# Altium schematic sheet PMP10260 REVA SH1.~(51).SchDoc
size 431 x 279 mm; Date: Not shown in title block; ApprovedBy: Not shown in title block; CheckedBy: Not shown in title block; Author: Not shown in title block; CompanyName: Not shown in title block; Engineer: Not shown in title block; Organization: Not shown in title block; Address1: Not shown in title block; Address2: Not shown in title block; Address3: Not shown in title block; Address4: Not shown in title block; DocumentNumber: 1; Revision: Use project parameter SCH_Rev; SheetNumber: 1; SheetTotal: 3; PageSetup: Record=PageOptions|CenterHorizontal=True|CenterVertical=True|PrintScale=1.00|XCorrection=1.00|YCorrection=1.00|PrintKind=0|BorderSize=5000000|LeftOffset=0|BottomOffset=0|Orientation=2|PaperLength=1000|PaperWidth=1000|Scale=100|PaperSource=15|PrintQuality=600|MediaType=1|DitherType=10|PaperKind=Letter|PrintScaleMode=1
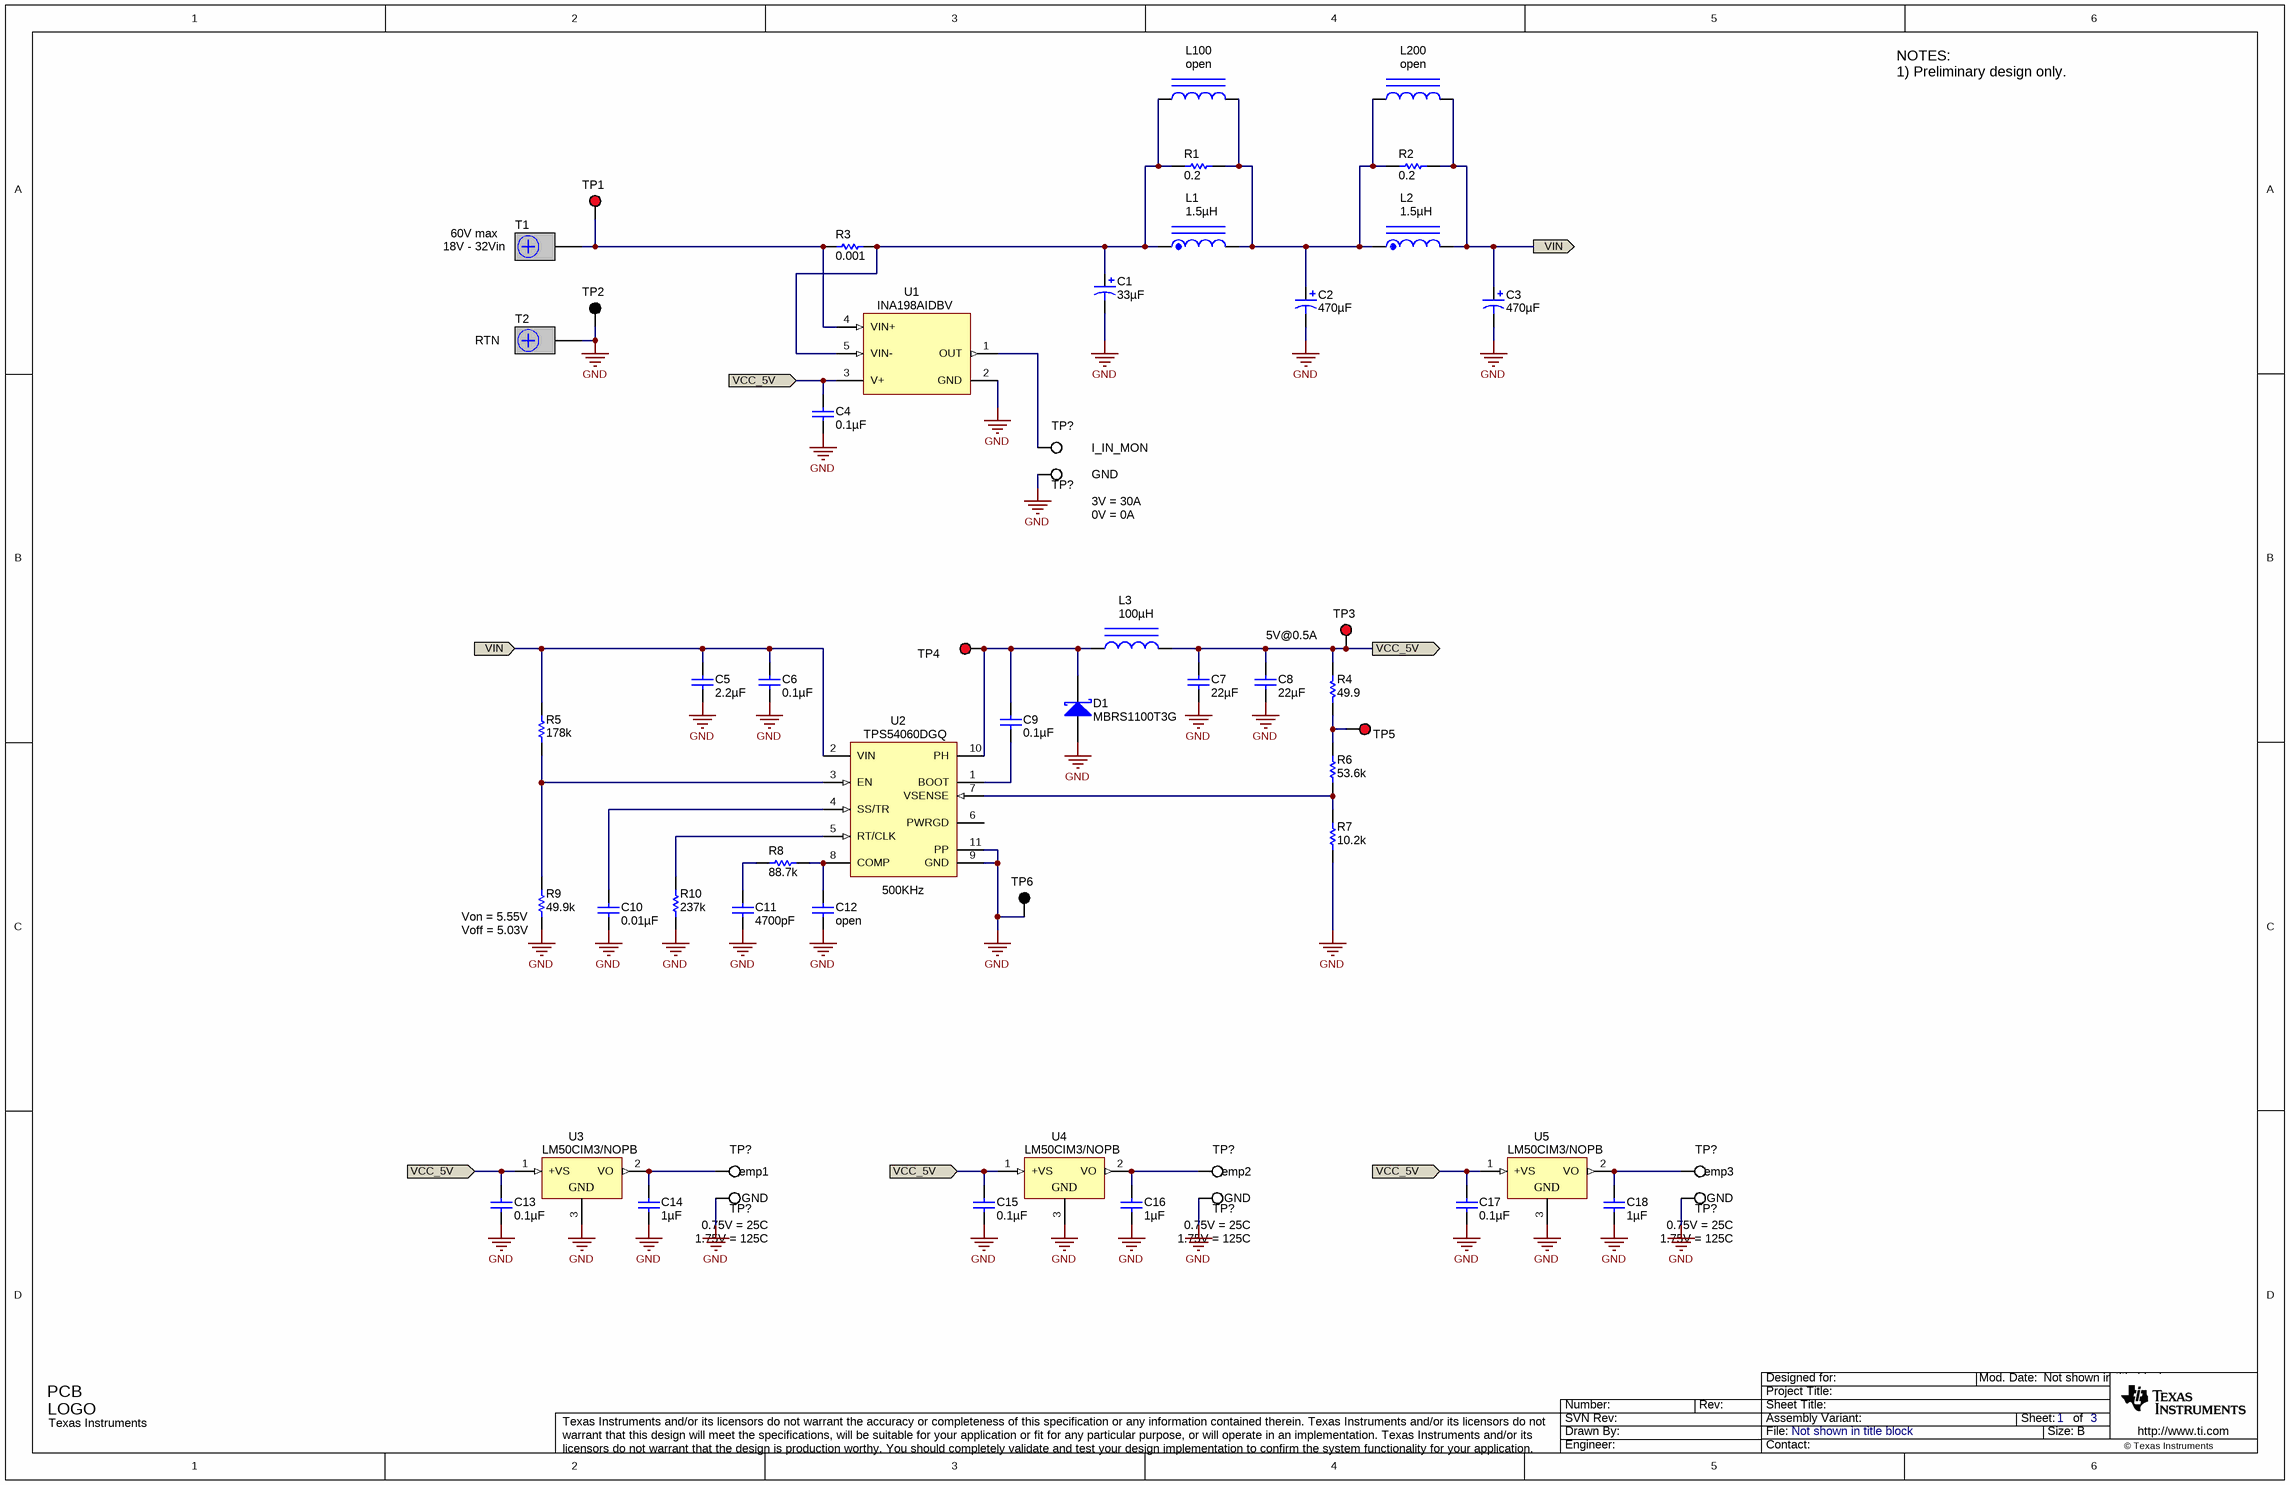
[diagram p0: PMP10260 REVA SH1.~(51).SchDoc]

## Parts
(Parts that share a designator on the sheet are numbered #1, #2 ... from top to bottom, then left to right.)
C1  ValueDisplayed: 33µF  [SXV_E12]  (hidden comment: 63SXV33M)
C2  ValueDisplayed: 470µF  [ZLH_1250x2500]  (hidden comment: 63ZLH470M12.5X25)
C3  ValueDisplayed: 470µF  [ZLH_1250x2500]  (hidden comment: 63ZLH470M12.5X25)
C4  ValueDisplayed: 0.1µF  [0603L]  (hidden comment: C1608X7R1H104K)
C5  ValueDisplayed: 2.2µF  [1210]  (hidden comment: GRM32ER72A225KA35L)
C6  ValueDisplayed: 0.1µF  [0603]  (hidden comment: GRM188R72A104KA35D)
C7  ValueDisplayed: 22µF  [1210]  (hidden comment: C3225X7R1C226M)
C8  ValueDisplayed: 22µF  [1210]  (hidden comment: C3225X7R1C226M)
C9  ValueDisplayed: 0.1µF  [0603]  (hidden comment: C1608X7R1H104K)
C10  ValueDisplayed: 0.01µF  [0603]  (hidden comment: C1608X7R1H103K)
C11  ValueDisplayed: 4700pF  [0603]  (hidden comment: C1608C0G1H472J)
C12  ValueDisplayed: open  [0603]
C13  ValueDisplayed: 0.1µF  [0603]  (hidden comment: C1608X7R1H104K)
C14  ValueDisplayed: 1µF  [0603]  (hidden comment: C1608X7R1E105K080AB)
C15  ValueDisplayed: 0.1µF  [0603]  (hidden comment: C1608X7R1H104K)
C16  ValueDisplayed: 1µF  [0603]  (hidden comment: C1608X7R1E105K080AB)
C17  ValueDisplayed: 0.1µF  [0603]  (hidden comment: C1608X7R1H104K)
C18  ValueDisplayed: 1µF  [0603]  (hidden comment: C1608X7R1E105K080AB)
D1  MBRS1100T3G  [SMB]
L1  ValueDisplayed: 1.5µH  [IND_PG1096]  (hidden comment: PG1096.152NL)
L2  ValueDisplayed: 1.5µH  [IND_PG1096]  (hidden comment: PG1096.152NL)
L3  ValueDisplayed: 100µH  [MSS1048]  (hidden comment: MSS1048-104MLB)
L100  ValueDisplayed: open  [SER2918]
L200  ValueDisplayed: open  [SER2918]
Logo1  Texas Instruments  [TI_Stacked_Overlay_Small]  (no BOM)
R1  value 0.2  [2512]  (hidden comment: CSRN2512FKR200)
R2  value 0.2  [2512]  (hidden comment: CSRN2512FKR200)
R3  value 0.001  [CSS2725_0005]  (hidden comment: CSS2725FT1L00)
R4  value 49.9  [0603]  (hidden comment: CRCW060349R9FKEA)
R5  value 178k  [0603]  (hidden comment: CRCW0603178KFKEA)
R6  value 53.6k  [0603]  (hidden comment: CRCW060353K6FKEA)
R7  value 10.2k  [0603]  (hidden comment: CRCW060310K2FKEA)
R8  value 88.7k  [0603]  (hidden comment: CRCW060388K7FKEA)
R9  value 49.9k  [0603]  (hidden comment: CRCW060349K9FKEA)
R10  value 237k  [0603]  (hidden comment: CRCW0603237KFKEA)
T1  CB35-36-CY  [CB35-36-CY]  (value not drawn)
T2  CB35-36-CY  [CB35-36-CY]  (value not drawn)
TP1  5010  [Keystone5010]  (value not drawn)
TP2  5011  [Keystone5011]  (value not drawn)
TP3  5010  [Keystone5010]  (value not drawn)
TP4  5010  [Keystone5010]  (value not drawn)
TP5  5010  [Keystone5010]  (value not drawn)
TP6  5011  [Keystone5011]  (value not drawn)
TP?#1  5015  [Testpoint_Keystone_Miniature]  (value not drawn)
TP?#2  5015  [Testpoint_Keystone_Miniature]  (value not drawn)
TP?#3  5015  [Testpoint_Keystone_Miniature]  (value not drawn)
TP?#4  5015  [Testpoint_Keystone_Miniature]  (value not drawn)
TP?#5  5015  [Testpoint_Keystone_Miniature]  (value not drawn)
TP?#6  5015  [Testpoint_Keystone_Miniature]  (value not drawn)
TP?#7  5015  [Testpoint_Keystone_Miniature]  (value not drawn)
TP?#8  5015  [Testpoint_Keystone_Miniature]  (value not drawn)
U1  INA198AIDBV  [DBV0005A_N]
U2  TPS54060DGQ  [DGQ0010D_N]
U3  LM50CIM3/NOPB  [MF03A_N]
U4  LM50CIM3/NOPB  [MF03A_N]
U5  LM50CIM3/NOPB  [MF03A_N]

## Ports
VCC_5V, VIN

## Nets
GND: C1.2(-) C2.2(-) C3.2(-) C4.2 C5.2 C6.2 C7.2 C8.2 C10.2 C11.2 C12.2 C13.2 C14.2 C15.2 C16.2 C17.2 C18.2 D1.2(A) R7.1 R9.1 R10.1 T2.1 TP2.1 TP6.1 TP?#2.1 TP?#6.1 TP?#7.1 TP?#8.1 U1.2(GND) U2.9(GND) U2.11(PP) U3.3(GND) U4.3(GND) U5.3(GND)
VCC_5V: C4.1 C7.1 C8.1 C13.1 C15.1 C17.1 L3.2 R4.2 TP3.1 U1.3(V+) U3.1(+VS) U4.1(+VS) U5.1(+VS) ; port VCC_5V
VIN: C3.1(+) C5.1 C6.1 L2.2 L200.2 R2.2 R5.2 U2.2(VIN) ; port VIN
NetC1_1: C1.1(+) L1.1 L100.1 R1.1 R3.2 U1.5(VIN-)
NetC2_1: C2.1(+) L1.2 L2.1 L100.2 L200.1 R1.2 R2.1
NetC9_1: C9.1 D1.1(K) L3.1 TP4.1 U2.10(PH)
NetC9_2: C9.2 U2.1(BOOT)
NetC10_1: C10.1 U2.4(SS/TR)
NetC11_1: C11.1 R8.2
NetC12_1: C12.1 R8.1 U2.8(COMP)
NetC14_1: C14.1 TP?#3.1 U3.2(VO)
NetC16_1: C16.1 TP?#4.1 U4.2(VO)
NetC18_1: C18.1 TP?#5.1 U5.2(VO)
NetR3_1: R3.1 T1.1 TP1.1 U1.4(VIN+)
NetR4_1: R4.1 R6.2 TP5.1
NetR5_1: R5.1 R9.2 U2.3(EN)
NetR6_1: R6.1 R7.2 U2.7(VSENSE)
NetR10_2: R10.2 U2.5(RT/CLK)
NetTP?#1_1: TP?#1.1 U1.1(OUT)

Not connected (* = marked no-connect by the designer): U2 6(PWRGD)

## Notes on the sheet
- NOTES:
  1) Preliminary design only.
- 60V max
- (near T1) 18V - 32Vin
- RTN
- (near TP?#2) 3V = 30A
- (near TP?#1) I_IN_MON
- (near TP?#2) GND
- (near TP?#2) 0V = 0A
- 5V@0.5A
- (near U2) 500KHz
- (near R9) Von = 5.55V
- (near R9) Voff = 5.03V
- (near TP?#3) Temp1
- (near TP?#4) Temp2
- (near TP?#5) Temp3
- (near TP?#6) 0.75V = 25C
- (near TP?#6) 1.75V = 125C
- (near TP?#6) GND
- (near TP?#7) 0.75V = 25C
- (near TP?#7) 1.75V = 125C
- (near TP?#7) GND
- (near TP?#8) 0.75V = 25C
- (near TP?#8) 1.75V = 125C
- (near TP?#8) GND

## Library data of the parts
C1 = 63SXV33M: CAP, OS-CON, 33uF, 63V, +/-20%, 0.025 ohm, 8.0x11.9mm SMD; Manufacturer: Panasonic; Polarized: Y; CompType: Capacitor; U/M: EA; Cap_F: 0.000033; Tolerance_%: 20; VDC_V: 63; ESR_Ohm: 0.025; IRMS_A: 2.95; TaMin_C: -55; TaMax_C: 105
C2 C3 = 63ZLH470M12.5X25: CAP, AL, 470uF, 63V, +/-20%, 0.043 ohm, TH; Manufacturer: Rubycon; Polarized: Y; CompType: Capacitor; U/M: EA; Cap_F: 0.00047; Tolerance_%: 20; VDC_V: 63; ESR_Ohm: 0.043; IRMS_A: 1.99; TaMin_C: -40; TaMax_C: 105
C4 = C1608X7R1H104K: CAP, CERM, 0.1uF, 50V, +/-10%, X7R, 0603; Manufacturer: TDK; Polarized: N; CompType: Capacitor; U/M: EA; Cap_F: 0.0000001; Tolerance_%: 10; ESR_Ohm: 0.017; Value1: 0.017 ohm; VDC_V: 50; TaMin_C: -55; TaMax_C: 125; Cap_Case: 0603
C5 = GRM32ER72A225KA35L: CAP, CERM, 2.2uF, 100V, +/-10%, X7R, 1210; Manufacturer: MuRata; Polarized: N; CompType: Capacitor; U/M: EA; Cap_F: 0.0000022; Tolerance_%: 10; ESR_Ohm: 0.007; Value1: 0.007 ohm; VDC_V: 100; IRMS_A: 4.4; TaMin_C: -55; TaMax_C: 125
C6 = GRM188R72A104KA35D: CAP, CERM, 0.1uF, 100V, +/-10%, X7R, 0603; Manufacturer: MuRata; Polarized: N; CompType: Capacitor; U/M: EA; Cap_F: 0.0000001; Tolerance_%: 10; Value1: Unknown; VDC_V: 100; TaMin_C: -55; TaMax_C: 125
C7 C8 = C3225X7R1C226M: CAP, CERM, 22uF, 16V, +/-20%, X7R, 1210; Manufacturer: TDK; Polarized: N; CompType: Capacitor; U/M: EA; Cap_F: 0.000022; Tolerance_%: 20; ESR_Ohm: 0.002; Value1: 0.002 ohm; VDC_V: 16; IRMS_A: 8.11; TaMin_C: -55; TaMax_C: 125
C9 C13 C15 C17 = C1608X7R1H104K: CAP, CERM, 0.1uF, 50V, +/-10%, X7R, 0603; Manufacturer: TDK; Polarized: N; CompType: Capacitor; U/M: EA; Cap_F: 0.0000001; Tolerance_%: 10; ESR_Ohm: 0.017; Value1: 0.017 ohm; VDC_V: 50; TaMin_C: -55; TaMax_C: 125
C10 = C1608X7R1H103K: CAP, CERM, 0.01uF, 50V, +/-10%, X7R, 0603; Manufacturer: TDK; Polarized: N; CompType: Capacitor; U/M: EA; Cap_F: 0.00000001; Tolerance_%: 10; ESR_Ohm: 0.0539; Value1: 0.0539 ohm; VDC_V: 50; TaMin_C: -55; TaMax_C: 125
C11 = C1608C0G1H332J: CAP, CERM, 4700pF, 50V, +/-5%, C0G/NP0, 0603; Manufacturer: TDK; Polarized: N; CompType: Capacitor; Value: 3300pF; U/M: EA; Cap_F: 0.0000000033; Tolerance_%: 5; ESR_Ohm: 0.0309; Value1: 0.0309 ohm; VDC_V: 50; TaMin_C: -55; TaMax_C: 125
C12 = C1608X7R1H104K: CAP, open, 0603; Polarized: N; CompType: Capacitor; U/M: EA; Cap_F: 0.0000001; Tolerance_%: 10; ESR_Ohm: 0.017; TempCo: X7R; TaMin_C: -55; TaMax_C: 125
C14 C16 C18 = C1608X7R1E105K080AB: CAP, CERM, 1uF, 25V, +/-10%, X7R, 0603; Manufacturer: TDK; Polarized: N; CompType: Capacitor; U/M: EA; Cap_F: 0.000001; Tolerance_%: 10; Value1: Unknown; VDC_V: 25; TaMin_C: -55; TaMax_C: 125
D1 = MBRS1100T3G: Diode, Schottky, 100V, 1A, SMB; Manufacturer: ON Semiconductor; U/M: EA; Vf_V: 0.75; Value2: 0.75V; Io_A: 1; Vr_V: 100; TJmax_C: 150; RJC_CperW: 22
L1 L2 = PG1096.252NL: Inductor, Shielded E Core, Ferrite, 1.5uH, 47A, 0.00085 ohm, SMD; Manufacturer: Pulse Engineering; SymbolCreator: a0412235; Ind_H: 1.5E-6; Imax_A: 47; Irms: 47A @ 40C rise; Isat: 55A @ 20% inductance drop
L3 = MSS1048-104MLB: Inductor, Shielded Drum Core, Ferrite, 100uH, 1.36A, 0.25 ohm, SMD; Manufacturer: Coilcraft; Ind_H: 100.0E-6; Imax_A: 1.36; Irms: 1.48A @ 40C rise; Isat: 1.36A @ 30% inductance drop; DCR_ohm: 0.25
L100 L200 = SER2918H-332KL: Inductor, open, SMD; Manufacturer: Pulse; Ind_H: 3.3E-6; Imax_A: 28; Irms: 28A @ 40C rise; Isat: 93.6A @ 30% inductance drop; DCR_ohm: 0.0026; Material: Ferrite
Logo1 = TI_Logo: Texas Instrument Corporate Signature; SymbolCreator: codlsc
R1 R2 = CSRN2512FKR200: RES, 0.2 ohm, 1%, 2W, 2512; Manufacturer: Stackpole Electronics Inc; CompType: Resistor; Value_Code: R200; Tolerance_%: 1; Power_W: 2; TempCo: 200 ppm/C; EIA_Code: E96; U/M: EA
R3 = CSS2725FTL500: RES, 0.001 ohm, 1%, 4W, RES_2725; Manufacturer: Stackpole Electronics Inc; CompType: Resistor; Res_ohm: 0.0005; Value_Code: R001; Tolerance_%: 1; Power_W: 4; TempCo: 50 ppm/C; U/M: EA
R4 = CRCW060349R9FKEA: RES, 49.9 ohm, 1%, 0.1W, 0603; Manufacturer: Vishay-Dale; CompType: Resistor; Value_Code: 49R9; Tolerance_%: 1; Power_W: 0.1; VDC_V: 75; TempCo: 100 ppm/C; EIA_Code: E96; U/M: EA
R5 = CRCW0603178KFKEA: RES, 178k ohm, 1%, 0.1W, 0603; Manufacturer: Vishay-Dale; CompType: Resistor; Res_ohm: 178000; Tolerance_%: 1; Power_W: 0.1; VDC_V: 75; TempCo: 100 ppm/C; EIA_Code: E96; U/M: EA
R6 = CRCW060353K6FKEA: RES, 53.6k ohm, 1%, 0.1W, 0603; Manufacturer: Vishay-Dale; CompType: Resistor; Res_ohm: 53600; Value_Code: 53k6; Tolerance_%: 1; Power_W: 0.1; VDC_V: 75; TempCo: 100 ppm/C; EIA_Code: E96; U/M: EA
R7 = CRCW060310K2FKEA: RES, 10.2k ohm, 1%, 0.1W, 0603; Manufacturer: Vishay-Dale; CompType: Resistor; Res_ohm: 10200; Value_Code: 10k2; Tolerance_%: 1; Power_W: 0.1; VDC_V: 75; TempCo: 100 ppm/C; EIA_Code: E96; U/M: EA
R8 = CRCW060388K7FKEA: RES, 88.7k ohm, 1%, 0.1W, 0603; Manufacturer: Vishay-Dale; CompType: Resistor; Res_ohm: 88700; Value_Code: 88k7; Tolerance_%: 1; Power_W: 0.1; VDC_V: 75; TempCo: 100 ppm/C; EIA_Code: E96; U/M: EA
R9 = CRCW060349K9FKEA: RES, 49.9k ohm, 1%, 0.1W, 0603; Manufacturer: Vishay-Dale; CompType: Resistor; Res_ohm: 49900; Value_Code: 49k9; Tolerance_%: 1; Power_W: 0.1; VDC_V: 75; TempCo: 100 ppm/C; EIA_Code: E96; U/M: EA
R10 = CRCW0603237KFKEA: RES, 237k ohm, 1%, 0.1W, 0603; Manufacturer: Vishay-Dale; CompType: Resistor; Res_ohm: 237000; Tolerance_%: 1; Power_W: 0.1; VDC_V: 75; TempCo: 100 ppm/C; EIA_Code: E96; U/M: EA
T1 T2 = CB35-36-CY: Terminal 50A Lug; Manufacturer: Panduit; SymbolCreator: crossc; CompType: Screw Terminal; U/M: EA
TP1 TP3-TP5 = 5010: Test Point, Multipurpose, Red, TH; Manufacturer: Keystone; CompType: Test Point Loop; U/M: EA
TP2 TP6 = 5011: Test Point, Multipurpose, Black, TH; Manufacturer: Keystone; CompType: Test Point Loop; U/M: EA
TP?#1-TP?#8 = 5015: Test Point, Miniature, SMT; Manufacturer: Keystone; CompType: Test Point Loop; U/M: EA
U1 = INA198AIDBV: CURRENT SHUNT MONITOR -16V to +80V Common-Mode Range, DBV0005A; Alternate Manufacturer: None; Manufacturer: Texas Instruments; SymbolCreator: a0411947; CompType: IC; U/M: EA
U2 = TPS54060DGQ: Buck Inverting Buck-Boost Step Down Regulator with 3.5 to 60 V Input and 0.8 to 58 V Output, -40 to 150 degC, 10-Pin MSOP-PowerPAD (DGQ), Green (RoHS & no Sb/Br); Manufacturer: Texas Instruments; Alternate Manufacturer: None; Alternate PartNumber: Equivalent; Duty Cycle(Max)(%): 98; Iout(Max)(A): 0.5; Iq(Typ)(mA): 0.116; Rating: Catalog; Regulated Outputs(#): 1; SubFamily: Step-Down Regulator; Switch Current Limit(Typ)(A): 0.6; Topology: Buck, Inverting Buck-Boost; Vin(Max)(V): 60; Vin(Min)(V): 3.5; Vout(Max)(V): 58; Vout(Min)(V): 0.8
U3-U5 = LM50CIM3/NOPB: Single-Supply Centigrade Temperature Sensor, 3-pin SOT-23, Pb-Free; Manufacturer: Texas Instruments; PackageTopMarking: T5C*XTT; PowerWise: N; CompType: Temp Sensor IC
